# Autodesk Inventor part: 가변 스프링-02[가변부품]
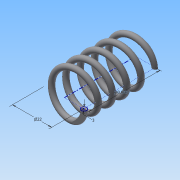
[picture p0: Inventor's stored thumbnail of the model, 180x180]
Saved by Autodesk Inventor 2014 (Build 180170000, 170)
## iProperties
Created: 2015-09
Part Number: 가변 스프링-02[가변부품]
Material: 강철, 탄소
Document SubType Name: Modeling
Designer: study
Density: 7.87 g/cm^3
Appearance: 반연마
Mass: 18.9154 g
Surface Area: 32.5802 cm^2
Volume: 2.40348 cm^3
Author: study
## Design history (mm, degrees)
sketch "스케치1"
  geometry: L1 (0, 0)-(11, 0); L2 (11, 0)-(11, 40.095); L3 (11, 40.095)-(0, 40.095); L4 (0, 40.095)-(0, 0); C1 r 1.5 at (11, 0)
  constraints: 8 end point, 2 parallel, 1 centre point, 1 coincident, 1 horizontal, 1 perpendicular
  dimensions: "d0" = 22 diameter of L2 L4; "d1" = 40.0955 distance of L1.end L2.end (derived); "d2" = 3 diameter of C1
feature "코일1" sketch "스케치1" pitch "d3" = 10; turns "d5" = 5; dims "d4" = 40.0955 (= d1), "d6" = 0, angle "d7" = 90 deg, angle "d8" = 90 deg, "d9" = 0, "d10" = 0
node "작업 평면1"
sketch "스케치2"
  geometry: L1 (-12.5, 0)-(-9.5, 0) reference; L2 (-12.5, 0)-(-9.5, 0) reference; 1 further point
  constraints: 2 horizontal alignment
extrude "돌출1" cut sketch "스케치2" stored distance "d12" = 10; taper "d13" = 0 deg
node "작업 평면2"
sketch "스케치3"
  geometry: L1 (-9.5, 0)-(-12.5, 0) reference; 1 further point
  constraints: 1 horizontal alignment
extrude "돌출2" cut sketch "스케치3" stored distance "d15" = 10; taper "d16" = 0 deg
node "솔리드1"
node "절단 모서리 투영1"
node "절단 모서리 투영2"
node "절단 모서리 투영3"
other parameters: "d11" = 0, "d14" = 40.0955 (= d1)
